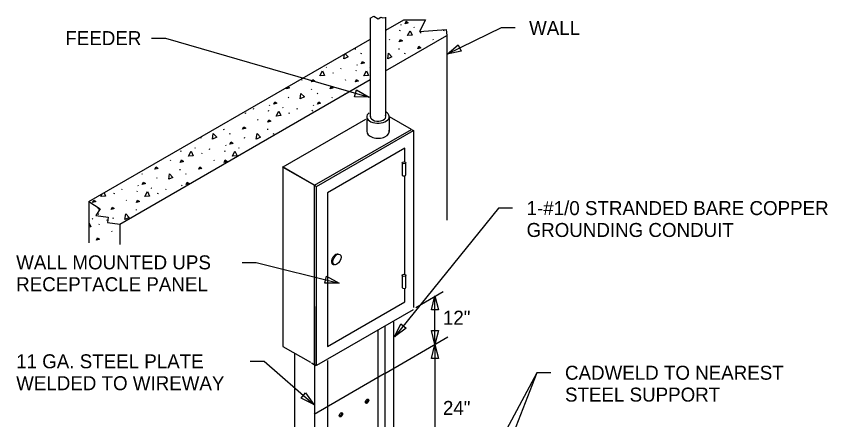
# Model space of a CAD drawing. Extents: x 10153.4 to 10196.4, y 9934.6 to 9978.8.
# Drawn here: x 10153.41 to 10192.01, y 9959.54 to 9978.75 of the extents above; entities that cross this region are included whole.
import ezdxf

# ---------------------------------------------------------------- set-up
doc = ezdxf.new("R2010")
doc.units = 0
for name, color, linetype in [('Level 60', 7, 'Continuous'), ('Level 61', 7, 'Continuous'), ('Level 62', 7, 'Continuous'), ('Level 63', 7, 'Continuous')]:
    doc.layers.add(name, color=color, linetype=linetype)

msp = doc.modelspace()

# ---------------------------------------------------------------- linework, layer by layer
at = {"layer": 'Level 60'}
for p, q in [((10157.312, 9969.57), (10157.331, 9969.612)), ((10157.029, 9969.124), (10157.048, 9969.096)), ((10156.865, 9968.928), (10156.956, 9968.724)), ((10156.956, 9968.724), (10156.865, 9968.716)), ((10157.359, 9968.83), (10157.377, 9968.872)), ((10157.733, 9969.033), (10157.752, 9969.075)), ((10157.937, 9968.534), (10157.955, 9968.507)), ((10157.221, 9968.084), (10157.276, 9968.199)), ((10157.369, 9968.13), (10157.221, 9968.084)), ((10157.276, 9968.199), (10157.369, 9968.13))]:
    msp.add_line(p, q, dxfattribs=at)
at = {"layer": 'Level 61'}
for p, q in [((10170.994, 9978.083), (10171.85, 9978.577)), ((10171.85, 9978.577), (10172.88, 9978.577)), ((10172.88, 9978.577), (10172.588, 9978.026)), ((10172.588, 9978.026), (10173.865, 9978.126)), ((10173.865, 9978.126), (10173.888, 9977.836)), ((10156.865, 9969.926), (10170.233, 9977.644)), ((10170.969, 9976.151), (10173.888, 9977.836)), ((10173.888, 9977.836), (10173.888, 9969.043)), ((10158.332, 9968.855), (10170.246, 9975.734)), ((10156.865, 9969.926), (10157.396, 9969.581)), ((10156.865, 9969.926), (10156.865, 9967.958)), ((10157.396, 9969.581), (10157.19, 9969.265)), ((10157.19, 9969.265), (10157.784, 9969.193)), ((10157.784, 9969.193), (10157.751, 9968.925)), ((10157.751, 9968.925), (10158.332, 9968.855)), ((10158.332, 9968.855), (10158.332, 9967.887)), ((10170.608, 9963.806), (10170.608, 9956.084)), ((10168.213, 9962.365), (10168.213, 9954.64)), ((10170.153, 9960.519), (10170.04, 9960.323)), ((10170.165, 9960.508), (10170.056, 9960.318)), ((10168.909, 9959.871), (10168.796, 9959.675)), ((10168.921, 9959.86), (10168.812, 9959.67))]:
    msp.add_line(p, q, dxfattribs=at)
for centre in [(10170.096, 9960.421), (10168.853, 9959.773)]:
    msp.add_ellipse(centre, major_axis=(0.0565, 0.0978), ratio=0.57735, dxfattribs=at)
at = {"layer": 'Level 62'}
for p, q in [((10170.246, 9978.655), (10170.415, 9978.755)), ((10170.415, 9978.755), (10170.627, 9978.627)), ((10170.246, 9978.649), (10170.246, 9973.969)), ((10170.627, 9978.627), (10170.75, 9978.717)), ((10170.75, 9978.717), (10170.844, 9978.683)), ((10170.844, 9978.683), (10170.98, 9978.693)), ((10170.98, 9978.707), (10170.98, 9974.007)), ((10171.694, 9978.365), (10171.713, 9978.337)), ((10171.906, 9978.397), (10171.962, 9978.512)), ((10172.054, 9978.443), (10171.906, 9978.397)), ((10171.962, 9978.512), (10172.054, 9978.443)), ((10171.659, 9978.06), (10171.678, 9978.101)), ((10172.022, 9977.829), (10172.147, 9978.064)), ((10172.147, 9978.064), (10172.244, 9977.847)), ((10172.317, 9978.247), (10172.336, 9978.219)), ((10172.646, 9977.953), (10172.665, 9977.995)), ((10173.742, 9978.06), (10173.761, 9978.101)), ((10171.141, 9977.657), (10171.16, 9977.63)), ((10171.627, 9977.537), (10171.682, 9977.653)), ((10171.775, 9977.583), (10171.627, 9977.537)), ((10171.682, 9977.653), (10171.775, 9977.583)), ((10172.244, 9977.847), (10172.026, 9977.829)), ((10173.224, 9977.657), (10173.243, 9977.63)), ((10169.525, 9977.214), (10169.53, 9977.172)), ((10171.609, 9977.214), (10171.613, 9977.172)), ((10172.508, 9977.207), (10172.564, 9977.322)), ((10172.656, 9977.253), (10172.508, 9977.207)), ((10172.564, 9977.322), (10172.656, 9977.253)), ((10168.996, 9976.731), (10169.026, 9976.947)), ((10169.198, 9976.824), (10169, 9976.732)), ((10169.06, 9976.967), (10169.198, 9976.824)), ((10169.814, 9976.968), (10169.832, 9977.01)), ((10171.079, 9976.731), (10171.116, 9976.995)), ((10171.282, 9976.824), (10171.084, 9976.732)), ((10171.116, 9976.995), (10171.282, 9976.824)), ((10171.897, 9976.968), (10171.915, 9977.01)), ((10169.611, 9976.45), (10169.629, 9976.423)), ((10169.823, 9976.483), (10169.878, 9976.598)), ((10169.971, 9976.529), (10169.823, 9976.483)), ((10169.878, 9976.598), (10169.971, 9976.529)), ((10167.855, 9975.914), (10167.98, 9976.15)), ((10167.98, 9976.15), (10168.077, 9975.933)), ((10168.15, 9976.333), (10168.169, 9976.305)), ((10168.48, 9976.039), (10168.498, 9976.081)), ((10168.854, 9976.242), (10168.873, 9976.284)), ((10169.576, 9976.146), (10169.594, 9976.187)), ((10169.939, 9975.914), (10170.063, 9976.15)), ((10170.063, 9976.15), (10170.161, 9975.933)), ((10170.234, 9976.333), (10170.252, 9976.305)), ((10166.974, 9975.743), (10166.993, 9975.715)), ((10167.46, 9975.623), (10167.515, 9975.739)), ((10167.608, 9975.669), (10167.46, 9975.623)), ((10167.515, 9975.739), (10167.608, 9975.669)), ((10168.077, 9975.933), (10167.86, 9975.914)), ((10169.058, 9975.743), (10169.076, 9975.715)), ((10169.543, 9975.623), (10169.599, 9975.739)), ((10169.691, 9975.669), (10169.543, 9975.623)), ((10169.599, 9975.739), (10169.691, 9975.669)), ((10170.161, 9975.933), (10169.943, 9975.914)), ((10166.258, 9975.292), (10166.296, 9975.371)), ((10166.406, 9975.339), (10166.258, 9975.292)), ((10166.334, 9975.393), (10166.406, 9975.339)), ((10167.442, 9975.3), (10167.447, 9975.258)), ((10168.342, 9975.292), (10168.397, 9975.408)), ((10168.49, 9975.339), (10168.342, 9975.292)), ((10168.397, 9975.408), (10168.49, 9975.339)), ((10166.35, 9974.864), (10166.369, 9974.906)), ((10166.913, 9974.817), (10166.949, 9975.081)), ((10167.115, 9974.91), (10166.917, 9974.818)), ((10166.949, 9975.081), (10167.115, 9974.91)), ((10167.73, 9975.054), (10167.749, 9975.096)), ((10168.433, 9974.864), (10168.452, 9974.906)), ((10169.025, 9975.029), (10169.033, 9975.081)), ((10169.033, 9975.081), (10169.062, 9975.05)), ((10165.444, 9974.536), (10165.463, 9974.508)), ((10165.656, 9974.568), (10165.712, 9974.684)), ((10165.804, 9974.615), (10165.656, 9974.568)), ((10165.712, 9974.684), (10165.804, 9974.615)), ((10167.527, 9974.536), (10167.546, 9974.508)), ((10167.74, 9974.568), (10167.795, 9974.684)), ((10167.888, 9974.615), (10167.74, 9974.568)), ((10167.795, 9974.684), (10167.888, 9974.615)), ((10164.313, 9974.125), (10164.331, 9974.167)), ((10164.688, 9974.328), (10164.706, 9974.37)), ((10165.409, 9974.231), (10165.428, 9974.273)), ((10165.772, 9974), (10165.897, 9974.236)), ((10165.897, 9974.236), (10165.994, 9974.019)), ((10166.067, 9974.418), (10166.086, 9974.391)), ((10166.396, 9974.125), (10166.415, 9974.167)), ((10166.771, 9974.328), (10166.789, 9974.37)), ((10167.492, 9974.231), (10167.511, 9974.273)), ((10164.891, 9973.829), (10164.91, 9973.801)), ((10165.377, 9973.709), (10165.432, 9973.824)), ((10165.525, 9973.755), (10165.377, 9973.709)), ((10165.432, 9973.824), (10165.525, 9973.755)), ((10165.994, 9974.019), (10165.776, 9974)), ((10170.025, 9973.843), (10166.094, 9971.573)), ((10170.079, 9973.956), (10170.079, 9973.242)), ((10171.156, 9973.98), (10171.156, 9973.266)), ((10172.206, 9973.366), (10171.161, 9973.969)), ((10163.275, 9973.385), (10163.28, 9973.344)), ((10164.175, 9973.378), (10164.231, 9973.494)), ((10164.323, 9973.424), (10164.175, 9973.378)), ((10164.231, 9973.494), (10164.323, 9973.424)), ((10165.359, 9973.385), (10165.363, 9973.344)), ((10166.294, 9973.452), (10166.314, 9973.494)), ((10166.314, 9973.494), (10166.337, 9973.477)), ((10167.598, 9970.705), (10172.206, 9973.366)), ((10172.206, 9973.366), (10172.299, 9973.308)), ((10162.183, 9972.95), (10162.202, 9972.992)), ((10162.746, 9972.902), (10162.783, 9973.167)), ((10162.948, 9972.996), (10162.75, 9972.904)), ((10162.783, 9973.167), (10162.948, 9972.996)), ((10163.564, 9973.14), (10163.582, 9973.181)), ((10164.267, 9972.95), (10164.285, 9972.992)), ((10164.829, 9972.902), (10164.866, 9973.167)), ((10165.032, 9972.996), (10164.834, 9972.904)), ((10164.866, 9973.167), (10165.032, 9972.996)), ((10165.647, 9973.14), (10165.665, 9973.181)), ((10167.695, 9970.649), (10172.299, 9973.308)), ((10172.299, 9973.308), (10172.299, 9964.881)), ((10163.361, 9972.622), (10163.379, 9972.594)), ((10163.573, 9972.654), (10163.628, 9972.77)), ((10163.721, 9972.7), (10163.573, 9972.654)), ((10163.628, 9972.77), (10163.721, 9972.7)), ((10161.242, 9972.317), (10161.261, 9972.359)), ((10161.605, 9972.086), (10161.73, 9972.322)), ((10161.73, 9972.322), (10161.827, 9972.104)), ((10161.9, 9972.504), (10161.919, 9972.476)), ((10162.23, 9972.211), (10162.248, 9972.252)), ((10162.604, 9972.414), (10162.623, 9972.455)), ((10163.326, 9972.317), (10163.344, 9972.359)), ((10163.689, 9972.086), (10163.813, 9972.322)), ((10163.813, 9972.322), (10163.911, 9972.104)), ((10163.984, 9972.504), (10164.002, 9972.476)), ((10171.896, 9972.474), (10168.212, 9970.347)), ((10171.896, 9971.82), (10171.896, 9972.474)), ((10160.724, 9971.915), (10160.743, 9971.887)), ((10161.21, 9971.795), (10161.265, 9971.91)), ((10161.358, 9971.841), (10161.21, 9971.795)), ((10161.265, 9971.91), (10161.358, 9971.841)), ((10161.827, 9972.104), (10161.61, 9972.086)), ((10162.808, 9971.915), (10162.826, 9971.887)), ((10163.293, 9971.795), (10163.349, 9971.91)), ((10163.441, 9971.841), (10163.293, 9971.795)), ((10163.349, 9971.91), (10163.441, 9971.841)), ((10163.911, 9972.104), (10163.693, 9972.086)), ((10160.008, 9971.464), (10160.064, 9971.58)), ((10160.156, 9971.51), (10160.008, 9971.464)), ((10160.064, 9971.58), (10160.156, 9971.51)), ((10161.192, 9971.471), (10161.197, 9971.429)), ((10162.092, 9971.464), (10162.147, 9971.58)), ((10162.24, 9971.51), (10162.092, 9971.464)), ((10162.147, 9971.58), (10162.24, 9971.51)), ((10167.583, 9970.711), (10166.076, 9971.581)), ((10166.091, 9971.575), (10166.091, 9963.033)), ((10166.094, 9971.573), (10167.598, 9970.705)), ((10171.761, 9971.774), (10171.761, 9971.192)), ((10171.944, 9971.192), (10171.944, 9971.774)), ((10159.397, 9971.226), (10159.415, 9971.267)), ((10160.1, 9971.036), (10160.119, 9971.078)), ((10160.663, 9970.988), (10160.699, 9971.252)), ((10160.865, 9971.081), (10160.667, 9970.99)), ((10160.699, 9971.252), (10160.865, 9971.081)), ((10161.48, 9971.226), (10161.499, 9971.267)), ((10171.896, 9966.466), (10171.896, 9971.162)), ((10159.194, 9970.708), (10159.213, 9970.68)), ((10159.406, 9970.74), (10159.462, 9970.856)), ((10159.554, 9970.786), (10159.406, 9970.74)), ((10159.462, 9970.856), (10159.554, 9970.786)), ((10161.277, 9970.708), (10161.296, 9970.68)), ((10161.49, 9970.74), (10161.545, 9970.856)), ((10161.638, 9970.786), (10161.49, 9970.74)), ((10161.545, 9970.856), (10161.638, 9970.786)), ((10167.598, 9962.165), (10167.598, 9970.705)), ((10167.598, 9970.705), (10167.695, 9970.649)), ((10167.695, 9962.121), (10167.695, 9970.649)), ((10157.439, 9970.172), (10157.504, 9970.295)), ((10157.591, 9970.345), (10157.661, 9970.19)), ((10158.063, 9970.297), (10158.081, 9970.338)), ((10158.438, 9970.5), (10158.456, 9970.541)), ((10159.159, 9970.403), (10159.178, 9970.445)), ((10159.522, 9970.172), (10159.647, 9970.408)), ((10159.647, 9970.408), (10159.744, 9970.19)), ((10159.817, 9970.59), (10159.836, 9970.562)), ((10160.146, 9970.297), (10160.165, 9970.338)), ((10160.521, 9970.5), (10160.539, 9970.541)), ((10168.212, 9970.347), (10168.212, 9963.026)), ((10157.043, 9969.88), (10157.099, 9969.996)), ((10157.191, 9969.927), (10157.043, 9969.88)), ((10157.099, 9969.996), (10157.191, 9969.927)), ((10157.661, 9970.19), (10157.443, 9970.172)), ((10158.641, 9970.001), (10158.66, 9969.973)), ((10159.127, 9969.88), (10159.182, 9969.996)), ((10159.275, 9969.927), (10159.127, 9969.88)), ((10159.182, 9969.996), (10159.275, 9969.927)), ((10159.744, 9970.19), (10159.526, 9970.172)), ((10157.925, 9969.55), (10157.981, 9969.665)), ((10158.073, 9969.596), (10157.925, 9969.55)), ((10157.981, 9969.665), (10158.073, 9969.596)), ((10159.109, 9969.557), (10159.113, 9969.515)), ((10157.314, 9969.311), (10157.332, 9969.353)), ((10158.017, 9969.122), (10158.035, 9969.163)), ((10158.579, 9969.074), (10158.616, 9969.338)), ((10158.782, 9969.167), (10158.584, 9969.076)), ((10158.616, 9969.338), (10158.782, 9969.167)), ((10171.761, 9966.419), (10171.761, 9965.838)), ((10171.944, 9965.838), (10171.944, 9966.419)), ((10171.896, 9965.153), (10171.896, 9965.799)), ((10167.6, 9964.934), (10167.6, 9954.546)), ((10168.212, 9963.026), (10171.896, 9965.153)), ((10172.288, 9964.776), (10167.689, 9962.121)), ((10171.361, 9964.198), (10171.361, 9956.856)), ((10170.942, 9963.999), (10170.942, 9952.601)), ((10166.091, 9963.033), (10167.402, 9962.276)), ((10166.639, 9962.693), (10166.639, 9951.094)), ((10167.456, 9962.245), (10167.583, 9962.171)), ((10167.583, 9962.179), (10167.674, 9962.127)), ((10167.598, 9962.173), (10167.598, 9954.644)), ((10170.917, 9961.722), (10167.573, 9959.792))]:
    msp.add_line(p, q, dxfattribs=at)
for centre, major_axis, start_param, end_param in [((10170.621, 9973.968), (0.535, 0), 2.47748, 7.118794), ((10170.621, 9973.968), (0.367, 0), 3.094276, 6.529635), ((10170.621, 9973.254), (0.535, 0), 3.074368, 6.501949), ((10171.853, 9971.201), (0.0914, 0), 3.382552, 6.221481), ((10168.599, 9967.175), (0.139, 0.24), 0.131424, 3.624754), ((10171.853, 9965.846), (0.0914, 0), 3.382552, 6.221481)]:
    msp.add_ellipse(centre, major_axis=major_axis, ratio=0.57735, start_param=start_param, end_param=end_param, dxfattribs=at)
for centre, major_axis in [((10171.853, 9971.774), (0.0914, 0)), ((10168.665, 9967.175), (0.139, 0.24)), ((10171.853, 9966.419), (0.0914, 0))]:
    msp.add_ellipse(centre, major_axis=major_axis, ratio=0.57735, dxfattribs=at)
at = {"layer": 'Level 63'}
for p, q in [((10176.469, 9978.196), (10173.9, 9976.954)), ((10177.136, 9978.196), (10176.469, 9978.196)), ((10159.845, 9977.711), (10160.512, 9977.711)), ((10160.512, 9977.711), (10170.193, 9974.897)), ((10176.351, 9969.617), (10171.408, 9963.48)), ((10177.018, 9969.617), (10176.351, 9969.617)), ((10164.151, 9967.033), (10164.818, 9967.033)), ((10164.818, 9967.033), (10168.77, 9966.049)), ((10173.713, 9965.629), (10172.423, 9964.874)), ((10173.327, 9963.115), (10173.327, 9965.447)), ((10173.327, 9963.116), (10173.327, 9965.37)), ((10173.935, 9963.472), (10170.942, 9961.722)), ((10173.327, 9963.116), (10173.327, 9960.693)), ((10173.327, 9963.116), (10173.327, 9957.671)), ((10164.534, 9962.321), (10165.201, 9962.321)), ((10165.201, 9962.321), (10167.569, 9960.259)), ((10178.178, 9961.778), (10172.623, 9951.481)), ((10178.178, 9961.778), (10173.97, 9950.984)), ((10178.845, 9961.778), (10178.178, 9961.778)), ((10178.845, 9961.778), (10178.178, 9961.778))]:
    msp.add_line(p, q, dxfattribs=at)
for points in [[(10174.573, 9977.094), (10173.9, 9976.954), (10174.428, 9977.394)], [(10169.599, 9975.244), (10170.193, 9974.897), (10169.506, 9974.923)], [(10168.163, 9966.371), (10168.77, 9966.049), (10168.083, 9966.048)], [(10173.16, 9964.78), (10173.327, 9965.447), (10173.494, 9964.78)], [(10171.956, 9963.894), (10171.408, 9963.48), (10171.697, 9964.104)], [(10173.494, 9963.782), (10173.327, 9963.115), (10173.16, 9963.782)], [(10173.16, 9962.45), (10173.327, 9963.116), (10173.494, 9962.45)], [(10167.176, 9960.823), (10167.569, 9960.259), (10166.957, 9960.571)]]:
    msp.add_lwpolyline(points, close=True, dxfattribs=at)

# ---------------------------------------------------------------- texts
for s, height, p in [('WALL', 0.6667, (10177.803, 9977.863)), ('FEEDER', 0.6667, (10155.746, 9977.378)), ('1-#1/0 STRANDED BARE COPPER', 0.66667, (10177.685, 9969.284)), ('GROUNDING CONDUIT', 0.66667, (10177.685, 9968.242)), ('WALL MOUNTED UPS', 0.66667, (10153.406, 9966.7)), ('RECEPTACLE PANEL', 0.66667, (10153.406, 9965.658)), ('12"', 0.6667, (10173.705, 9964.065)), ('11 GA. STEEL PLATE', 0.66667, (10153.406, 9961.988)), ('CADWELD TO NEAREST', 0.66667, (10179.512, 9961.444)), ('WELDED TO WIREWAY', 0.66667, (10153.406, 9960.946)), ('STEEL SUPPORT', 0.66667, (10179.512, 9960.403)), ('24"', 0.6667, (10173.705, 9959.767))]:
    msp.add_text(s, height=height, dxfattribs=at).set_placement(p)

doc.saveas('drawing.dxf')
